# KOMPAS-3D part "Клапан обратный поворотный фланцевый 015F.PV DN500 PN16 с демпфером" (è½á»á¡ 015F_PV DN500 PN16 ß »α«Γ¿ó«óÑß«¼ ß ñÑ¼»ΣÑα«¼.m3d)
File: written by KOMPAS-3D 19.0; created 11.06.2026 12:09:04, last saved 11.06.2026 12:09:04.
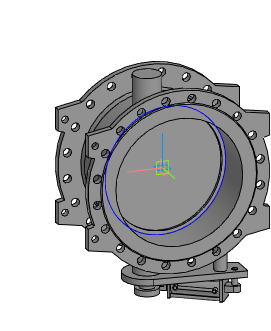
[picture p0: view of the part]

Document properties: Автор: Энергия; Полное имя файла: Z:\3.Личные\kachalov\001_3d для проектировщиков\5.5 Тип 015F.PV Клапан обратный поворотный с двумя эксцентриками\_stp_Клапан 015F.PV DN300-DN1200 с противовесом с демпфером\Клапан 015F_PV DN500 PN16 с противовесом с демпфером.m3d

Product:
- Part/product: Клапан обратный поворотный фланцевый 015F.PV DN500 PN16 с демпфером

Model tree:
1. Операция без истории:1
2. Сплайн:1
     Координата Y = 30; Координата Z = 250; Вес = 1; Координата X = 500; Координата Y = 95.8262; Координата Z = 250; Вес = 0.333333; Координата X = 500; Координата Y = 95.8262; Координата Z = -250; Вес = 0.333333; Координата Y = 30; Координата Z = -250; Вес = 1; Координата X = -500; Координата Y = -35.8262; Координата Z = -250; Вес = 0.333333; Координата X = -500; Координата Y = -35.8262; Координата Z = 250; Вес = 0.333333; Порядок = 4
